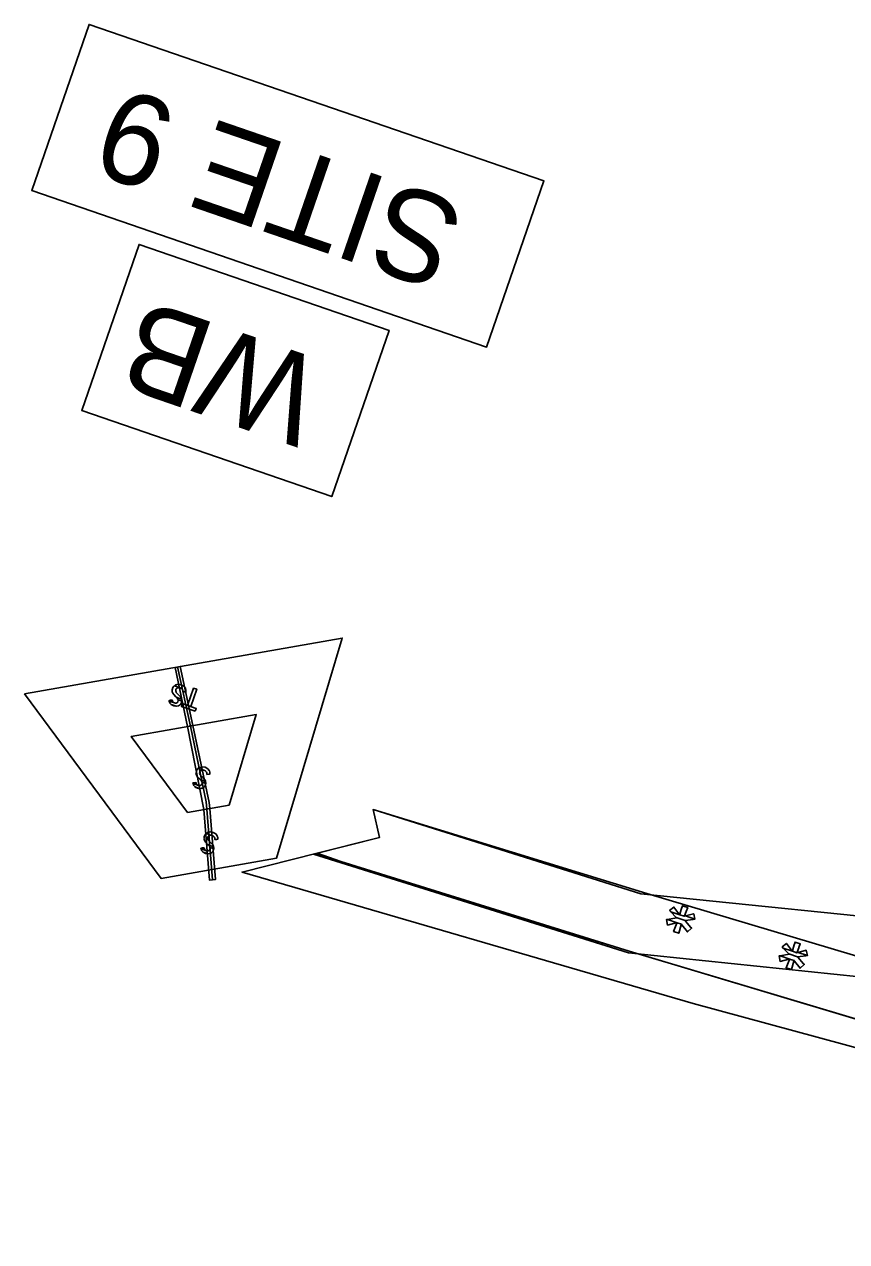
# Model space of a CAD drawing. Extents: x 474218 to 481634, y 484357 to 504997.
# Drawn here: x 480170.7 to 480306.7, y 493362.5 to 493563.9 of the extents above; entities that cross this region are included whole.
import ezdxf

# ---------------------------------------------------------------- set-up
doc = ezdxf.new("R2010")
doc.units = 0
for name, color, linetype in [('Old_Level_29', 7, 'Continuous'), ('Old_Level_30', 7, 'Continuous'), ('Prop Boundary Clearing Mechanized Hatching CELL', 7, 'Continuous'), ('Prop Earthen Structure Fill In Wetlands Hatching CELL', 7, 'Continuous'), ('Prop Earthen Structure Impacts In Surface Waters Hatching CELL', 7, 'Continuous'), ('Prop Grid Mask', 7, 'Continuous'), ('Scratch_Level_4', 7, 'Continuous'), ('Temp Earthen Structure Impacts In Surface Waters Hatching CELL', 7, 'Continuous')]:
    doc.layers.add(name, color=color, linetype=linetype)

msp = doc.modelspace()

# ---------------------------------------------------------------- linework, layer by layer
at = {"layer": 'Old_Level_29'}
msp.add_lwpolyline([(480247.13, 493510.51), (480171.91, 493536.43), (480181.38, 493563.93), (480256.61, 493538.01)], close=True, dxfattribs=at)
at = {"layer": 'Old_Level_30'}
msp.add_lwpolyline([(480221.52, 493485.78), (480180.18, 493500.02), (480189.65, 493527.52), (480230.99, 493513.28)], close=True, dxfattribs=at)
at = {"layer": 'Prop Boundary Clearing Mechanized Hatching CELL'}
msp.add_lwpolyline([(480415.42, 493366.6), (480425.75, 493372.43), (480417.94, 493376.58), (480369.1, 493390.86), (480321.48, 493405.8), (480273.61, 493420.1), (480228.36, 493434), (480229.42, 493429.39), (480218.67, 493426.67), (480270.68, 493410.54), (480318.55, 493396.23), (480366.2, 493381.29), (480414.15, 493367.27), (480415.42, 493366.6)], dxfattribs=at)
for points in [[(480278.94, 493416.74), (480278.09, 493417.85), (480277.39, 493417.27), (480277.57, 493417.08), (480279.07, 493416.57)], [(480280.13, 493417.15), (480280.38, 493417.78), (480279.5, 493418.08), (480279.32, 493417.43), (480279.32, 493417.43), (480279.1, 493416.68), (480279.07, 493416.58), (480279.81, 493416.33), (480279.85, 493416.43), (480280.13, 493417.15)], [(480278.59, 493415.26), (480278.63, 493415.27), (480277.06, 493415.81), (480277.02, 493415.81), (480276.86, 493415.78), (480277.05, 493414.88), (480278.46, 493415.23)], [(480279.99, 493415.55), (480279.94, 493415.61), (480278.47, 493416.12), (480278.53, 493416.06), (480277.06, 493415.81), (480278.63, 493415.27), (480278.62, 493415.25), (480279.34, 493415.01), (480279.42, 493414.9), (480280.34, 493413.76), (480280.34, 493413.75), (480281.03, 493414.35), (480280.94, 493414.45), (480280.91, 493414.49)], [(480281.31, 493415.81), (480281.54, 493415.84), (480279.99, 493416.38), (480279.81, 493416.33), (480279.07, 493416.58), (480279.07, 493416.57), (480277.57, 493417.08), (480278.47, 493416.12), (480279.94, 493415.61), (480281.28, 493415.8)], [(480281.37, 493416.72), (480281.36, 493416.73), (480281.35, 493416.73), (480279.99, 493416.38), (480281.54, 493415.84)], [(480279.32, 493414.94), (480279.34, 493415.01), (480278.62, 493415.25), (480278.59, 493415.19), (480278.04, 493413.83), (480278.9, 493413.53)], [(480297.56, 493410.72), (480296.71, 493411.84), (480296.02, 493411.26), (480296.19, 493411.07), (480297.69, 493410.55)], [(480298.76, 493411.14), (480299, 493411.77), (480298.13, 493412.07), (480297.94, 493411.42), (480297.94, 493411.41), (480297.73, 493410.67), (480297.7, 493410.56), (480298.43, 493410.31), (480298.47, 493410.41), (480298.75, 493411.13)], [(480297.21, 493409.25), (480297.25, 493409.26), (480295.68, 493409.8), (480295.64, 493409.79), (480295.49, 493409.77), (480295.67, 493408.86), (480297.08, 493409.22)], [(480298.61, 493409.54), (480298.56, 493409.6), (480297.1, 493410.1), (480297.15, 493410.04), (480295.68, 493409.8), (480297.25, 493409.26), (480297.24, 493409.24), (480297.96, 493408.99), (480298.05, 493408.88), (480298.97, 493407.74), (480298.97, 493407.74), (480299.65, 493408.33), (480299.56, 493408.44), (480299.53, 493408.47)], [(480299.94, 493409.79), (480300.17, 493409.83), (480298.62, 493410.36), (480298.43, 493410.31), (480297.7, 493410.56), (480297.69, 493410.55), (480296.19, 493411.07), (480297.1, 493410.1), (480298.56, 493409.6), (480299.9, 493409.79)], [(480299.99, 493410.71), (480299.99, 493410.72), (480299.98, 493410.71), (480298.62, 493410.36), (480300.17, 493409.83)], [(480297.94, 493408.92), (480297.96, 493408.99), (480297.24, 493409.24), (480297.21, 493409.17), (480296.66, 493407.82), (480297.53, 493407.52)]]:
    msp.add_lwpolyline(points, close=True, dxfattribs=at)
at = {"layer": 'Prop Earthen Structure Fill In Wetlands Hatching CELL'}
for p, q in [((480270.68, 493410.54), (480223.01, 493425.42)), ((480318.55, 493396.23), (480270.68, 493410.54))]:
    msp.add_line(p, q, dxfattribs=at)
msp.add_lwpolyline([(480223.01, 493425.42), (480219.09, 493426.77), (480206.68, 493423.64), (480281.31, 493401.9), (480335.71, 493387.11), (480408.15, 493362.49), (480415.42, 493366.6)], dxfattribs=at)
at = {"layer": 'Prop Earthen Structure Impacts In Surface Waters Hatching CELL'}
msp.add_line((480200.35, 493433.98), (480200.35, 493433.98), dxfattribs=at)
for points in [[(480201.26, 493435.16), (480198.55, 493447.88), (480197.67, 493447.72), (480200.35, 493433.98), (480201.34, 493434.15), (480201.26, 493435.16)], [(480200.35, 493433.98), (480200.35, 493433.98), (480201.29, 493422.33), (480202.29, 493422.41), (480201.34, 493434.15), (480200.35, 493433.98), (480200.35, 493433.98), (480200.35, 493433.98)]]:
    msp.add_lwpolyline(points, dxfattribs=at)
for points in [[(480200.16, 493440.54), (480200.38, 493440.5), (480199.45, 493440.82), (480199.42, 493440.79), (480199.42, 493440.79), (480199.41, 493440.79), (480199.34, 493440.73), (480199.33, 493440.71), (480199.32, 493440.69), (480199.26, 493440.6), (480199.24, 493440.56), (480199.22, 493440.53), (480199.15, 493440.41), (480199.13, 493440.33), (480199.09, 493440.14), (480199.07, 493440.05), (480199.08, 493439.98), (480199.11, 493439.82), (480199.11, 493439.82), (480199.13, 493439.7), (480199.19, 493439.61), (480199.34, 493439.38), (480199.4, 493439.32), (480199.64, 493439.06), (480199.77, 493438.94), (480200.66, 493438.63), (480200.62, 493438.73), (480200.52, 493438.93), (480200.47, 493438.99), (480200.25, 493439.25), (480200.14, 493439.36), (480199.97, 493439.53), (480199.77, 493439.74), (480199.73, 493439.83), (480199.67, 493439.94), (480199.68, 493440.14), (480199.71, 493440.22), (480199.77, 493440.34), (480199.8, 493440.37), (480199.84, 493440.4), (480199.92, 493440.48), (480199.96, 493440.49), (480200.01, 493440.5), (480200.13, 493440.54), (480200.15, 493440.54)], [(480201.01, 493440.76), (480200.58, 493440.99), (480200.08, 493441.08), (480200.08, 493441.08), (480199.69, 493440.98), (480199.64, 493440.97), (480199.45, 493440.82), (480200.38, 493440.5), (480200.62, 493440.38), (480200.62, 493440.38), (480200.64, 493440.36), (480200.74, 493440.25), (480200.78, 493440.21), (480200.79, 493440.18), (480200.84, 493440.06), (480200.86, 493440), (480200.86, 493439.96), (480200.87, 493439.82), (480201.18, 493439.86), (480201.26, 493439.86), (480201.37, 493439.88), (480201.37, 493439.98), (480201.37, 493440.01), (480201.37, 493440.04), (480201.37, 493440.11), (480201.37, 493440.12), (480201.37, 493440.12), (480201.35, 493440.17), (480201.28, 493440.4), (480201.27, 493440.43), (480201.01, 493440.75)], [(480199.12, 493438.32), (480199.06, 493438.47), (480198.79, 493438.43), (480198.7, 493438.42), (480198.57, 493438.4), (480198.57, 493438.37), (480198.57, 493438.36), (480198.58, 493438.34), (480198.58, 493438.31), (480199.5, 493437.99), (480199.28, 493438.1), (480199.25, 493438.13), (480199.24, 493438.14), (480199.21, 493438.18), (480199.14, 493438.27)], [(480200.66, 493438.19), (480200.7, 493438.32), (480200.07, 493438.53), (480200.1, 493438.39), (480200.05, 493438.2), (480200.04, 493438.18), (480200.01, 493438.15), (480199.92, 493438.04), (480199.86, 493438.02), (480199.78, 493437.98), (480199.74, 493437.97), (480199.71, 493437.97), (480199.62, 493437.98), (480199.5, 493437.99), (480198.58, 493438.31), (480198.59, 493438.24), (480198.68, 493438.02), (480198.7, 493437.97), (480198.93, 493437.73), (480199.76, 493437.45), (480200.05, 493437.51), (480200.13, 493437.52), (480200.31, 493437.64), (480200.37, 493437.69), (480200.4, 493437.71), (480200.43, 493437.72), (480200.43, 493437.73), (480200.45, 493437.75), (480200.48, 493437.8), (480200.51, 493437.84), (480200.58, 493437.95), (480200.61, 493437.99), (480200.61, 493438)], [(480200.67, 493438.55), (480200.66, 493438.63), (480199.77, 493438.94), (480199.91, 493438.81), (480200.05, 493438.6), (480200.07, 493438.53), (480200.7, 493438.32), (480200.69, 493438.38)], [(480199.72, 493437.45), (480199.76, 493437.45), (480198.93, 493437.73), (480198.94, 493437.72), (480199.33, 493437.52), (480199.34, 493437.52)], [(480201.48, 493429.74), (480201.7, 493429.71), (480200.77, 493430.03), (480200.74, 493430), (480200.73, 493430), (480200.73, 493429.99), (480200.66, 493429.94), (480200.65, 493429.91), (480200.63, 493429.9), (480200.58, 493429.8), (480200.56, 493429.77), (480200.54, 493429.73), (480200.47, 493429.62), (480200.45, 493429.54), (480200.4, 493429.34), (480200.38, 493429.26), (480200.4, 493429.18), (480200.43, 493429.03), (480200.43, 493429.03), (480200.45, 493428.91), (480200.51, 493428.81), (480200.66, 493428.58), (480200.72, 493428.52), (480200.96, 493428.27), (480201.09, 493428.14), (480201.98, 493427.84), (480201.94, 493427.93), (480201.84, 493428.14), (480201.79, 493428.19), (480201.57, 493428.45), (480201.46, 493428.56), (480201.29, 493428.73), (480201.09, 493428.94), (480201.04, 493429.03), (480200.99, 493429.14), (480201, 493429.35), (480201.03, 493429.42), (480201.09, 493429.55), (480201.12, 493429.57), (480201.15, 493429.61), (480201.24, 493429.69), (480201.28, 493429.7), (480201.33, 493429.71), (480201.45, 493429.74), (480201.47, 493429.74)], [(480202.33, 493429.96), (480201.9, 493430.19), (480201.4, 493430.28), (480201.4, 493430.28), (480201.01, 493430.18), (480200.96, 493430.17), (480200.77, 493430.03), (480201.7, 493429.71), (480201.94, 493429.58), (480201.94, 493429.58), (480201.96, 493429.57), (480202.06, 493429.46), (480202.1, 493429.41), (480202.11, 493429.39), (480202.16, 493429.26), (480202.18, 493429.21), (480202.18, 493429.17), (480202.19, 493429.03), (480202.5, 493429.06), (480202.58, 493429.07), (480202.68, 493429.08), (480202.69, 493429.19), (480202.69, 493429.21), (480202.69, 493429.24), (480202.69, 493429.31), (480202.68, 493429.32), (480202.68, 493429.33), (480202.67, 493429.37), (480202.6, 493429.61), (480202.59, 493429.64), (480202.33, 493429.96)], [(480201.99, 493427.75), (480201.98, 493427.84), (480201.09, 493428.14), (480201.23, 493428.02), (480201.37, 493427.81), (480201.39, 493427.74), (480202.02, 493427.52), (480202.01, 493427.59)], [(480200.44, 493427.52), (480200.38, 493427.68), (480200.11, 493427.64), (480200.02, 493427.62), (480199.89, 493427.6), (480199.89, 493427.57), (480199.89, 493427.57), (480199.89, 493427.54), (480199.9, 493427.51), (480200.82, 493427.19), (480200.6, 493427.3), (480200.57, 493427.33), (480200.56, 493427.34), (480200.53, 493427.38), (480200.46, 493427.47)], [(480201.98, 493427.4), (480202.01, 493427.52), (480201.39, 493427.74), (480201.42, 493427.59), (480201.36, 493427.4), (480201.36, 493427.39), (480201.33, 493427.35), (480201.24, 493427.25), (480201.18, 493427.22), (480201.09, 493427.19), (480201.06, 493427.17), (480201.03, 493427.18), (480200.94, 493427.18), (480200.82, 493427.19), (480199.9, 493427.51), (480199.9, 493427.44), (480200, 493427.23), (480200.02, 493427.18), (480200.25, 493426.93), (480201.08, 493426.65), (480201.37, 493426.71), (480201.45, 493426.73), (480201.63, 493426.85), (480201.69, 493426.89), (480201.72, 493426.91), (480201.75, 493426.93), (480201.75, 493426.93), (480201.77, 493426.96), (480201.8, 493427.01), (480201.82, 493427.05), (480201.9, 493427.15), (480201.92, 493427.19), (480201.93, 493427.21)], [(480201.03, 493426.66), (480201.08, 493426.65), (480200.25, 493426.93), (480200.26, 493426.92), (480200.65, 493426.73), (480200.65, 493426.73)]]:
    msp.add_lwpolyline(points, close=True, dxfattribs=at)
at = {"layer": 'Prop Grid Mask'}
for points in [[(480256.61, 493538.01), (480181.38, 493563.93), (480171.91, 493536.43), (480247.13, 493510.51)], [(480230.99, 493513.28), (480189.65, 493527.52), (480180.18, 493500.02), (480221.52, 493485.78)]]:
    msp.add_lwpolyline(points, close=True, dxfattribs=at)
at = {"layer": 'Scratch_Level_4'}
msp.add_line((480198.16, 493447.79), (480196.04, 493457.61), dxfattribs=at)
for points in [[(480170.69, 493453.14), (480223.25, 493462.36), (480212.38, 493425.94), (480193.31, 493422.59)], [(480198.55, 493447.88), (480197.67, 493447.72), (480195.64, 493457.52), (480196.46, 493457.66)], [(480197.67, 493447.72), (480195.64, 493457.52), (480196.46, 493457.66), (480198.55, 493447.88)], [(480204.56, 493434.72), (480197.67, 493433.51), (480188.36, 493446.09), (480209.04, 493449.72)], [(480202.29, 493422.41), (480201.34, 493434.15), (480201.26, 493435.16), (480199.39, 493443.96), (480198.55, 493447.88), (480197.67, 493447.72), (480200.35, 493433.98), (480201.29, 493422.33)], [(480201.34, 493434.15), (480202.29, 493422.41), (480201.29, 493422.33), (480200.35, 493433.98)], [(480430.45, 493375.08), (480442.63, 493381.98), (480420.87, 493389.25), (480372.89, 493403.37), (480323.53, 493414.84), (480272.61, 493420.06), (480228.36, 493434), (480229.42, 493429.39), (480218.67, 493426.67), (480270.61, 493410.31), (480321.5, 493405), (480370.34, 493393.7), (480418.07, 493379.07)]]:
    msp.add_lwpolyline(points, close=True, dxfattribs=at)
for points in [[(480200.85, 493434.07), (480200.75, 493435.27), (480198.16, 493447.79)], [(480200.85, 493434.07), (480200.85, 493434.07)], [(480201.79, 493422.37), (480200.85, 493434.07)], [(480228.36, 493434), (480229.42, 493429.39), (480218.48, 493426.63)], [(480442.63, 493381.98), (480420.87, 493389.25), (480372.89, 493403.37), (480323.53, 493414.84), (480272.61, 493420.06), (480228.36, 493434)], [(480218.48, 493426.63), (480270.61, 493410.31), (480321.5, 493405), (480370.34, 493393.7), (480418.07, 493379.07), (480430.45, 493375.08)]]:
    msp.add_lwpolyline(points, dxfattribs=at)
at = {"layer": 'Temp Earthen Structure Impacts In Surface Waters Hatching CELL'}
msp.add_lwpolyline([(480198.55, 493447.88), (480196.46, 493457.66), (480195.64, 493457.52), (480197.67, 493447.72), (480198.55, 493447.88)], dxfattribs=at)
for points in [[(480196.2, 493454.18), (480196.43, 493454.14), (480195.5, 493454.46), (480195.46, 493454.43), (480195.46, 493454.43), (480195.45, 493454.42), (480195.38, 493454.37), (480195.37, 493454.35), (480195.36, 493454.33), (480195.3, 493454.24), (480195.28, 493454.2), (480195.26, 493454.17), (480195.19, 493454.05), (480195.17, 493453.97), (480195.13, 493453.78), (480195.11, 493453.69), (480195.12, 493453.61), (480195.15, 493453.46), (480195.15, 493453.46), (480195.17, 493453.34), (480195.24, 493453.25), (480195.39, 493453.01), (480195.44, 493452.96), (480195.68, 493452.7), (480195.82, 493452.58), (480196.7, 493452.27), (480196.66, 493452.36), (480196.56, 493452.57), (480196.51, 493452.63), (480196.29, 493452.88), (480196.18, 493452.99), (480196.01, 493453.17), (480195.81, 493453.38), (480195.77, 493453.46), (480195.72, 493453.57), (480195.72, 493453.78), (480195.75, 493453.86), (480195.81, 493453.98), (480195.84, 493454.01), (480195.88, 493454.04), (480195.96, 493454.12), (480196, 493454.13), (480196.05, 493454.14), (480196.18, 493454.17), (480196.19, 493454.18)], [(480197.05, 493454.4), (480196.62, 493454.63), (480196.12, 493454.72), (480196.12, 493454.72), (480195.73, 493454.62), (480195.68, 493454.61), (480195.5, 493454.46), (480196.43, 493454.14), (480196.66, 493454.02), (480196.67, 493454.01), (480196.68, 493454), (480196.78, 493453.89), (480196.83, 493453.85), (480196.84, 493453.82), (480196.88, 493453.69), (480196.9, 493453.64), (480196.9, 493453.6), (480196.91, 493453.46), (480197.22, 493453.49), (480197.3, 493453.5), (480197.41, 493453.51), (480197.41, 493453.62), (480197.41, 493453.65), (480197.41, 493453.67), (480197.41, 493453.75), (480197.41, 493453.76), (480197.41, 493453.76), (480197.39, 493453.81), (480197.33, 493454.04), (480197.32, 493454.07), (480197.06, 493454.39)], [(480198.23, 493451.04), (480199.21, 493453.89), (480198.67, 493454.08), (480197.69, 493451.22)], [(480195.16, 493451.96), (480195.11, 493452.11), (480194.83, 493452.07), (480194.74, 493452.06), (480194.61, 493452.04), (480194.61, 493452.01), (480194.62, 493452), (480194.62, 493451.98), (480194.62, 493451.94), (480195.54, 493451.63), (480195.32, 493451.73), (480195.29, 493451.77), (480195.28, 493451.78), (480195.25, 493451.82), (480195.18, 493451.91)], [(480196.71, 493451.83), (480196.74, 493451.95), (480196.11, 493452.17), (480196.14, 493452.02), (480196.09, 493451.83), (480196.08, 493451.82), (480196.05, 493451.78), (480195.96, 493451.68), (480195.9, 493451.66), (480195.82, 493451.62), (480195.78, 493451.61), (480195.75, 493451.61), (480195.66, 493451.62), (480195.54, 493451.63), (480194.62, 493451.94), (480194.63, 493451.88), (480194.72, 493451.66), (480194.74, 493451.61), (480194.98, 493451.37), (480195.8, 493451.08), (480196.1, 493451.14), (480196.17, 493451.16), (480196.35, 493451.28), (480196.42, 493451.33), (480196.45, 493451.35), (480196.47, 493451.36), (480196.47, 493451.37), (480196.49, 493451.39), (480196.52, 493451.44), (480196.55, 493451.48), (480196.62, 493451.59), (480196.65, 493451.63), (480196.66, 493451.64)], [(480196.71, 493452.19), (480196.7, 493452.27), (480195.82, 493452.58), (480195.95, 493452.45), (480196.09, 493452.24), (480196.11, 493452.17), (480196.74, 493451.95), (480196.73, 493452.02)], [(480195.76, 493451.09), (480195.8, 493451.08), (480194.98, 493451.37), (480194.99, 493451.36), (480195.38, 493451.16), (480195.38, 493451.16)], [(480198.95, 493450.27), (480199.11, 493450.73), (480196.81, 493451.53), (480196.65, 493451.06)]]:
    msp.add_lwpolyline(points, close=True, dxfattribs=at)

# ---------------------------------------------------------------- texts
at = {"layer": 'Old_Level_29'}
msp.add_text('SITE 9', height=15, rotation=160.9896, dxfattribs=at).set_placement((480244.17, 493533.83))
at = {"layer": 'Old_Level_30'}
msp.add_text('WB', height=15, rotation=160.9896, dxfattribs=at).set_placement((480220.85, 493508.03))

doc.saveas('drawing.dxf')
